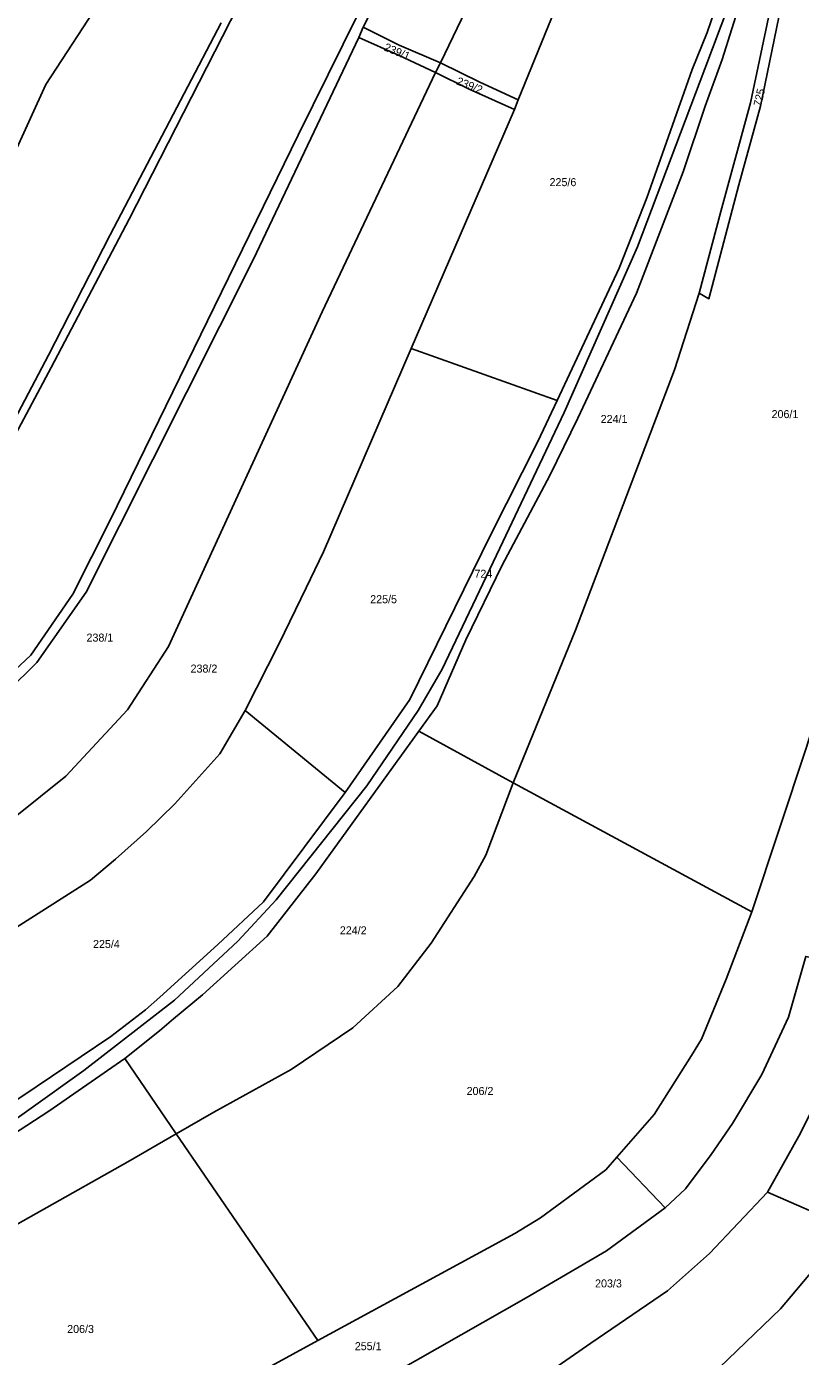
# Model space of a CAD drawing. Extents: x -629983 to -626385, y -1072828 to -1067897.
# Drawn here: x -629247.5 to -628957.6, y -1072098.9 to -1071600.2 of the extents above; entities that cross this region are included whole.
import ezdxf

# ---------------------------------------------------------------- set-up
doc = ezdxf.new("R2010")
doc.units = 0
for name, color, linetype in [('Parcela nároku', 7, 'Continuous'), ('Parcelní číslo', 7, 'Continuous'), ('silnice III třídy', 7, 'Continuous')]:
    doc.layers.add(name, color=color, linetype=linetype)

msp = doc.modelspace()

# ---------------------------------------------------------------- linework, layer by layer
at = {"layer": 'Parcela nároku'}
for points in [[(-629072.5, -1071439.34), (-629068.16, -1071389.85), (-629059.12, -1071295.53), (-629054.11, -1071282.33), (-629016.96, -1071260.9), (-628953.27, -1071223.79), (-628874.74, -1071182.64), (-628860.9, -1071175.58), (-628810.99, -1071148.78), (-628800.11, -1071179.66), (-628924.47, -1071246.62), (-629016.09, -1071299.47), (-629036.98, -1071313.01), (-629041.43, -1071320.98), (-629055.63, -1071492.48), (-629060.14, -1071524.48), (-629067.98, -1071560.03), (-629081.5, -1071590.96), (-629092.49, -1071613.87), (-629107.98, -1071607.26), (-629121.43, -1071600.5), (-629095.73, -1071550.33), (-629083.31, -1071517.04), (-629076.19, -1071476.02)], [(-628924.47, -1071246.62), (-628800.11, -1071179.66), (-628786.42, -1071209.23), (-628822.8, -1071229.07), (-628863.15, -1071251.54), (-628902.72, -1071274.77), (-629022.6, -1071343.59), (-629023.33, -1071362.72), (-629026.51, -1071416.63), (-629029.38, -1071456.91), (-629034.21, -1071516.22), (-629039.71, -1071562.2), (-629041.24, -1071568.96), (-629048.3, -1071590.92), (-629063.32, -1071627.75), (-629077.7, -1071621.02), (-629092.49, -1071613.87), (-629081.5, -1071590.96), (-629067.98, -1071560.03), (-629060.14, -1071524.48), (-629055.63, -1071492.48), (-629041.43, -1071320.98), (-629036.98, -1071313.01), (-629016.09, -1071299.47)], [(-629181.93, -1071526.51), (-629213.07, -1071488.18), (-629230.03, -1071518.34), (-629245.72, -1071546.08), (-629274.4, -1071590.15), (-629285.46, -1071610.49), (-629297.99, -1071634.37), (-629324.25, -1071677.09), (-629316.52, -1071720.63), (-629312.72, -1071760.83), (-629294.09, -1071730.4), (-629271.01, -1071689.19), (-629240.34, -1071621.97), (-629196.55, -1071554.87)], [(-628881.16, -1071520.32), (-628931.77, -1071565.67), (-628943.05, -1071574.49), (-628950.98, -1071580.24), (-628964.79, -1071587.97), (-628965.6, -1071596.64), (-628972.55, -1071630.1), (-628980.65, -1071659.6), (-628991.86, -1071702.29), (-628995.57, -1071700.14), (-629004.75, -1071728.91), (-629041.83, -1071826.52), (-629065.15, -1071883.82), (-628975.79, -1071932.13), (-628955.34, -1071870.39), (-628936, -1071807.64), (-628918.1, -1071746.5), (-628903.12, -1071685.36), (-628893.13, -1071622.33), (-628888.59, -1071593.56), (-628885.49, -1071566.88), (-628884.1, -1071555.94)], [(-628969.07, -1071594.46), (-628976.29, -1071628.8), (-628987.33, -1071669.61), (-628995.57, -1071700.14), (-628991.86, -1071702.29), (-628980.65, -1071659.6), (-628972.55, -1071630.1), (-628965.6, -1071596.64), (-628964.79, -1071587.97), (-628962.16, -1071539.51), (-628965.89, -1071548.89)], [(-629001.53, -1071654.71), (-629018.98, -1071700.15), (-629041.03, -1071747.11), (-629051.51, -1071768.53), (-629069.35, -1071802.21), (-629082.93, -1071830.2), (-629093.74, -1071854.92), (-629100.59, -1071864.42), (-629065.15, -1071883.82), (-629041.83, -1071826.52), (-629004.75, -1071728.91), (-628995.57, -1071700.14), (-628987.33, -1071669.61), (-628976.29, -1071628.8), (-628969.07, -1071594.46), (-628965.89, -1071548.89), (-628976.08, -1071577.91), (-628986.87, -1071612.61), (-628993.31, -1071630.03)], [(-629041.24, -1071568.96), (-629048.3, -1071590.92), (-629063.32, -1071627.75), (-629064.76, -1071631.28), (-629103.38, -1071720.91), (-629048.7, -1071740.39), (-629025.54, -1071690.8), (-629015.12, -1071664.5), (-628998.13, -1071616.37), (-628992.5, -1071602.39), (-628988.12, -1071589.54)], [(-629225.17, -1071812.32), (-629162.67, -1071687.67), (-629123.05, -1071604.28), (-629107.86, -1071611.13), (-629094.31, -1071617.41), (-629136.71, -1071707.14), (-629194.34, -1071832.69), (-629209.67, -1071856.49), (-629232.87, -1071881.31), (-629251.74, -1071896.54), (-629316.66, -1071940.57), (-629329.21, -1071909.93), (-629289.77, -1071880.97), (-629265.83, -1071860.49), (-629243.72, -1071838.67)], [(-629123.05, -1071604.28), (-629121.43, -1071600.5), (-629107.98, -1071607.26), (-629092.49, -1071613.87), (-629094.31, -1071617.41), (-629107.86, -1071611.13)], [(-629077.7, -1071621.02), (-629063.32, -1071627.75), (-629064.76, -1071631.28), (-629081.69, -1071623.72), (-629094.31, -1071617.41), (-629092.49, -1071613.87)], [(-629081.69, -1071623.72), (-629094.31, -1071617.41), (-629136.71, -1071707.14), (-629194.34, -1071832.69), (-629209.67, -1071856.49), (-629232.87, -1071881.31), (-629251.74, -1071896.54), (-629316.66, -1071940.57), (-629303.12, -1071970.89), (-629223.63, -1071920.25), (-629214.19, -1071912.47), (-629202.54, -1071902), (-629191.92, -1071891.73), (-629175.07, -1071872.99), (-629165.6, -1071856.64), (-629152.85, -1071831.58), (-629142.82, -1071810.63), (-629136.23, -1071797.23), (-629103.38, -1071720.91), (-629064.76, -1071631.28)], [(-629142.82, -1071810.63), (-629152.85, -1071831.58), (-629165.6, -1071856.64), (-629128.17, -1071887.39), (-629103.93, -1071852.57), (-629073.55, -1071790.66), (-629055.91, -1071755.82), (-629048.7, -1071740.39), (-629103.38, -1071720.91), (-629136.23, -1071797.23)], [(-629214.19, -1071912.47), (-629202.54, -1071902), (-629191.92, -1071891.73), (-629175.07, -1071872.99), (-629165.6, -1071856.64), (-629128.17, -1071887.39), (-629158.77, -1071928.4), (-629175.81, -1071944.47), (-629197.54, -1071964.19), (-629203.01, -1071968.89), (-629215.9, -1071978.97), (-629249.31, -1072001.47), (-629283.84, -1072023.61), (-629305.85, -1071972.63), (-629303.12, -1071970.89), (-629223.63, -1071920.25)], [(-629139.18, -1071917.95), (-629100.59, -1071864.42), (-629065.15, -1071883.82), (-629075.42, -1071910.94), (-629079.82, -1071918.88), (-629095.92, -1071943.89), (-629108.48, -1071960.16), (-629125.28, -1071975.71), (-629148.4, -1071991.27), (-629177.37, -1072007.28), (-629191.45, -1072015.43), (-629210.65, -1071987.13), (-629197.67, -1071976.83), (-629192.5, -1071972.27), (-629181.57, -1071963.3), (-629157.36, -1071941.3)], [(-628938.22, -1071976.5), (-628958.18, -1072016.34), (-628969.96, -1072037.34), (-628940.49, -1072050.12), (-628928.03, -1072029.41), (-628913.94, -1071994.53), (-628895.63, -1071943.01), (-628883.29, -1071905.76), (-628874.28, -1071875.78), (-628902.8, -1071867.23), (-628930.34, -1071953.64)], [(-629075.42, -1071910.94), (-629079.82, -1071918.88), (-629095.92, -1071943.89), (-629108.48, -1071960.16), (-629125.28, -1071975.71), (-629148.4, -1071991.27), (-629177.37, -1072007.28), (-629191.45, -1072015.43), (-629138.38, -1072092.9), (-629064.54, -1072052.77), (-629054.95, -1072046.92), (-629030.5, -1072028.89), (-629026.31, -1072024.11), (-629012.39, -1072008.2), (-628998.34, -1071986.07), (-628994.67, -1071979.92), (-628985.39, -1071957.38), (-628975.79, -1071932.13), (-629065.15, -1071883.82)], [(-628930.34, -1071953.64), (-628955.55, -1071948.91), (-628962.01, -1071971.7), (-628972.04, -1071993.16), (-628983, -1072011.55), (-628991.02, -1072023.18), (-629000.69, -1072036.07), (-629008.31, -1072043.17), (-629030.22, -1072059.23), (-629060.33, -1072076.95), (-629167.62, -1072138.03), (-629199.41, -1072156.52), (-629198.64, -1072156.73), (-629176.85, -1072157.84), (-629144.86, -1072164.27), (-629127.22, -1072151.26), (-629053.24, -1072105.84), (-629036.15, -1072093.96), (-629007.41, -1072074.28), (-628991.59, -1072060.34), (-628969.96, -1072037.34), (-628958.18, -1072016.34), (-628938.22, -1071976.5)], [(-629210.65, -1071987.13), (-629191.45, -1072015.43), (-629209.53, -1072025.89), (-629274.46, -1072062.37), (-629317.36, -1072086.21), (-629332.98, -1072064.82), (-629288.06, -1072038.62), (-629239.15, -1072006.97)], [(-628991.19, -1072106.11), (-629013.78, -1072123.63), (-629044.57, -1072142.1), (-629053.74, -1072152.89), (-629021.27, -1072149.18), (-628980.82, -1072145.62), (-628974.82, -1072136.89), (-628967.92, -1072127.37), (-628963.17, -1072121.94), (-628929.9, -1072088.75), (-628926.96, -1072084.96), (-628913.9, -1072061.88), (-628890.28, -1072015.69), (-628887.02, -1072007.08), (-628913.94, -1071994.53), (-628928.03, -1072029.41), (-628940.49, -1072050.12), (-628950.42, -1072063.7), (-628965.05, -1072080.99)], [(-629138.38, -1072092.9), (-629191.45, -1072015.43), (-629209.53, -1072025.89), (-629274.46, -1072062.37), (-629317.36, -1072086.21), (-629279.88, -1072136.87), (-629270.47, -1072138.37), (-629257.89, -1072140.54), (-629236.18, -1072146.64), (-629186.65, -1072119.27)], [(-629138.38, -1072092.9), (-629064.54, -1072052.77), (-629054.95, -1072046.92), (-629030.5, -1072028.89), (-629026.31, -1072024.11), (-629008.31, -1072043.17), (-629030.22, -1072059.23), (-629060.33, -1072076.95), (-629167.62, -1072138.03), (-629199.41, -1072156.52), (-629236.18, -1072146.64), (-629186.65, -1072119.27)], [(-629127.22, -1072151.26), (-629144.86, -1072164.27), (-629143.38, -1072164.57), (-629125.03, -1072164.68), (-629113.23, -1072164.35), (-629091.43, -1072160.11), (-629085.85, -1072158.87), (-629068.42, -1072155.5), (-629053.74, -1072152.89), (-629044.57, -1072142.1), (-629013.78, -1072123.63), (-628991.19, -1072106.11), (-628965.05, -1072080.99), (-628950.42, -1072063.7), (-628940.49, -1072050.12), (-628969.96, -1072037.34), (-628991.59, -1072060.34), (-629007.41, -1072074.28), (-629036.15, -1072093.96), (-629053.24, -1072105.84)]]:
    msp.add_lwpolyline(points, close=True, dxfattribs=at)
for points in [[(-629270.1, -1071787.66), (-629238.27, -1071728.02), (-629209.11, -1071672.42), (-629142.04, -1071541)], [(-629270.1, -1071787.66), (-629238.27, -1071728.02), (-629209.11, -1071672.42), (-629142.04, -1071541)], [(-629100.62, -1071549.6), (-629145.79, -1071640.95), (-629216.16, -1071785.29), (-629230.17, -1071813.06), (-629245.92, -1071835.99), (-629291.14, -1071878.24)], [(-629100.62, -1071549.6), (-629145.79, -1071640.95), (-629216.16, -1071785.29), (-629230.17, -1071813.06), (-629245.92, -1071835.99), (-629291.14, -1071878.24)], [(-629196.55, -1071554.87), (-629240.34, -1071621.97), (-629271.01, -1071689.19)], [(-629265.83, -1071860.49), (-629243.72, -1071838.67), (-629225.17, -1071812.32), (-629162.67, -1071687.67), (-629123.05, -1071604.28), (-629121.43, -1071600.5), (-629095.73, -1071550.33)], [(-628976.08, -1071577.91), (-628986.87, -1071612.61), (-628993.31, -1071630.03), (-629001.53, -1071654.71), (-629018.98, -1071700.15), (-629041.03, -1071747.11), (-629051.51, -1071768.53), (-629069.35, -1071802.21), (-629082.93, -1071830.2), (-629093.74, -1071854.92), (-629100.59, -1071864.42), (-629139.18, -1071917.95), (-629157.36, -1071941.3), (-629181.57, -1071963.3), (-629192.5, -1071972.27), (-629197.67, -1071976.83), (-629210.65, -1071987.13), (-629239.15, -1072006.97), (-629288.06, -1072038.62)], [(-629249.31, -1072001.47), (-629215.9, -1071978.97), (-629203.01, -1071968.89), (-629197.54, -1071964.19), (-629175.81, -1071944.47), (-629158.77, -1071928.4), (-629128.17, -1071887.39), (-629103.93, -1071852.57), (-629073.55, -1071790.66), (-629055.91, -1071755.82), (-629048.7, -1071740.39), (-629025.54, -1071690.8), (-629015.12, -1071664.5), (-628998.13, -1071616.37), (-628992.5, -1071602.39), (-628988.12, -1071589.54)], [(-629270.94, -1071783.31), (-629239.29, -1071723.45), (-629216.17, -1071678.37), (-629174.6, -1071598.82)], [(-629174.6, -1071598.82), (-629216.17, -1071678.37), (-629239.29, -1071723.45), (-629270.94, -1071783.31)], [(-628955.34, -1071870.39), (-628975.79, -1071932.13), (-628985.39, -1071957.38), (-628994.67, -1071979.92), (-628998.34, -1071986.07), (-629012.39, -1072008.2), (-629026.31, -1072024.11), (-629008.31, -1072043.17), (-629000.69, -1072036.07), (-628991.02, -1072023.18), (-628983, -1072011.55), (-628972.04, -1071993.16), (-628962.01, -1071971.7), (-628955.55, -1071948.91)]]:
    msp.add_lwpolyline(points, dxfattribs=at)
at = {"layer": 'silnice III třídy'}
msp.add_lwpolyline([(-628972.14, -1071559.6), (-628993.43, -1071616.06), (-629018.59, -1071682.79), (-629046.09, -1071744.98), (-629070.23, -1071795.78), (-629091.79, -1071841.15), (-629100.81, -1071856.73), (-629120.01, -1071884.96), (-629154.03, -1071927.71), (-629168.43, -1071943.14), (-629192.14, -1071965.25), (-629226.04, -1071991.73), (-629285.39, -1072034.08)], dxfattribs=at)

# ---------------------------------------------------------------- texts
at = {"layer": 'Parcelní číslo'}
for s, rotation, p in [('239/1', 337.6199, (-629113.86, -1071609.07)), ('239/2', 338.3592, (-629086.72, -1071621.83)), ('725', 77.19, (-628972.28, -1071630.39))]:
    msp.add_text(s, height=3, rotation=rotation, dxfattribs=at).set_placement(p)
for s, p in [('225/6', (-629051.57, -1071660.06)), ('206/1', (-628968.38, -1071747.04)), ('224/1', (-629032.42, -1071748.88)), ('724', (-629079.71, -1071806.9)), ('225/5', (-629118.77, -1071816.45)), ('238/1', (-629225.07, -1071830.84)), ('238/2', (-629186.08, -1071842.46)), ('224/2', (-629130.15, -1071940.62)), ('225/4', (-629222.63, -1071945.74)), ('206/2', (-629082.65, -1072000.85)), ('203/3', (-629034.51, -1072073.01)), ('206/3', (-629232.32, -1072090.1)), ('255/1', (-629124.56, -1072096.54))]:
    msp.add_text(s, height=3, dxfattribs=at).set_placement(p)

doc.saveas('drawing.dxf')
